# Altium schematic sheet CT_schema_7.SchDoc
size 147 x 119 mm
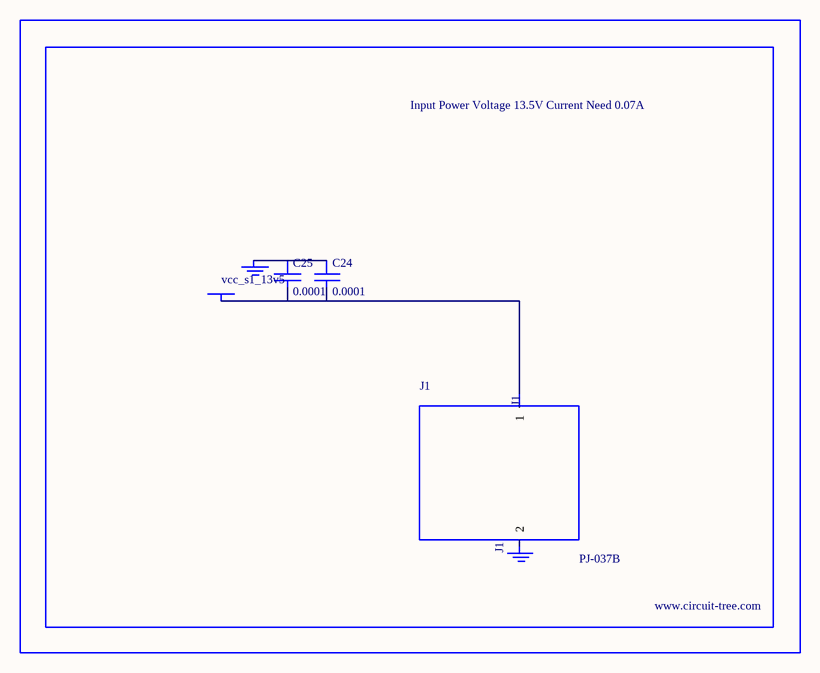
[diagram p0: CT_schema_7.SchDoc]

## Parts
BORDER6  (no value)
C24  0.0001  [EXV-9H]
C25  0.0001  [EXV-9H]
GND_INSTANCE_6_0  (no value)
GND_INSTANCE_6_1  (no value)
J1  PJ-037B  [PJ-037B_PACKAGE]
POWER_INSTANCE_6_0  vcc_s1_13v5

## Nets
NetC24_1: C24.1 C25.1 GND_INSTANCE_6_0.0(GND)
NetC24_2: C24.2 C25.2 J1.1 POWER_INSTANCE_6_0.0(PWR)

Not connected (* = marked no-connect by the designer): GND_INSTANCE_6_1 0(GND); J1 2

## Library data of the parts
BORDER6 = BORDER_PAGE6
C24 C25 = EDK107M035A9HAA
GND_INSTANCE_6_0 GND_INSTANCE_6_1 = GND
POWER_INSTANCE_6_0 = PWR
